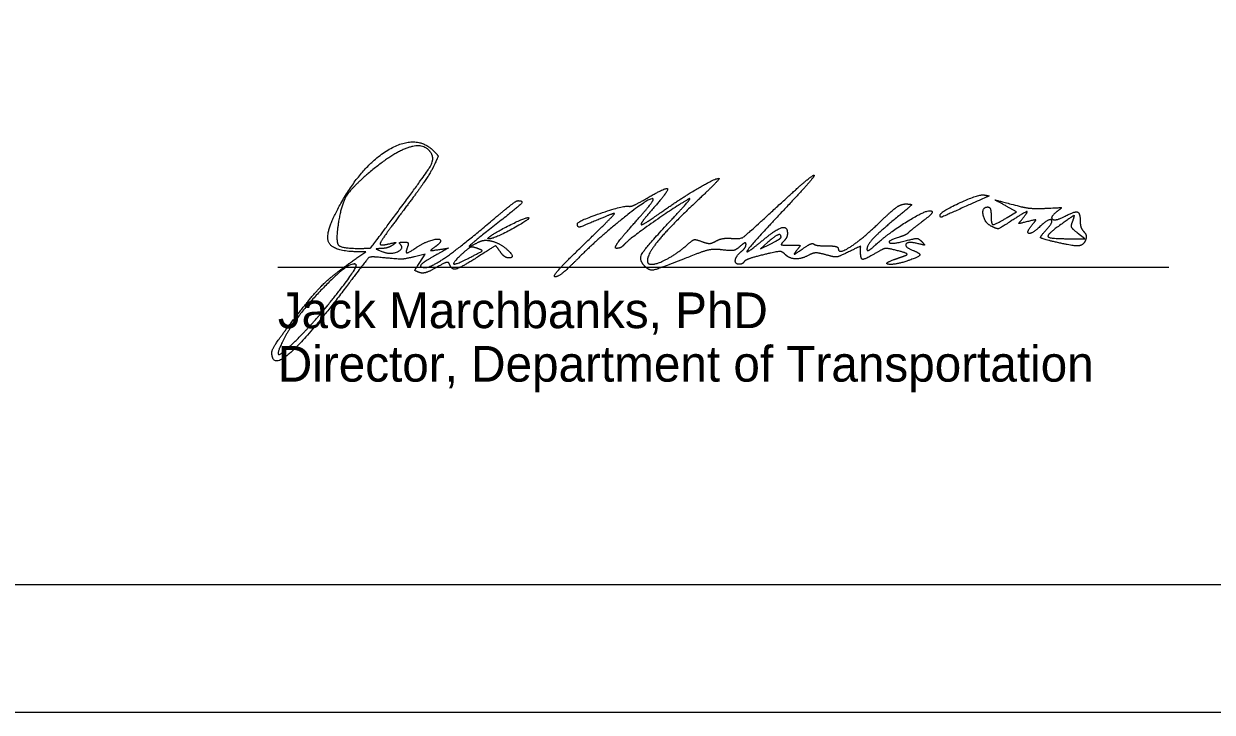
# Model space of a CAD drawing. Extents: x 0 to 34, y 0 to 22.
# Drawn here: x 25.002 to 29.67, y 0 to 2.703 of the extents above; entities that cross this region are included whole.
import ezdxf

# ---------------------------------------------------------------- set-up
doc = ezdxf.new("R2010")
doc.units = 0
for name, color, linetype in [('SH_Border', 7, 'Continuous'), ('SH_Cut_Line', 7, 'Continuous'), ('SH_Data', 7, 'Continuous'), ('SH_Text', 7, 'Continuous')]:
    doc.layers.add(name, color=color, linetype=linetype)

msp = doc.modelspace()

# ---------------------------------------------------------------- linework, layer by layer
at = {"layer": 'SH_Border'}
msp.add_lwpolyline([(1.5, 21.5), (33.5, 21.5), (33.5, 0.5), (1.5, 0.5)], close=True, dxfattribs=at)
at = {"layer": 'SH_Cut_Line'}
msp.add_lwpolyline([(0, 0), (34, 0), (34, 22), (0, 22)], close=True, dxfattribs=at)
at = {"layer": 'SH_Data'}
msp.add_line((26, 1.7478), (29.5, 1.7478), dxfattribs=at)
at = {"layer": 'SH_Text'}
for p, q in [((26.4623, 1.9529), (26.4623, 1.9529)), ((28.6016, 1.952), (28.6016, 1.952)), ((26.7828, 1.8214), (26.7828, 1.8214)), ((26.8276, 1.863), (26.8276, 1.863)), ((27.1995, 1.834), (27.1995, 1.834)), ((27.9766, 1.865), (27.9766, 1.865)), ((29.0541, 1.8458), (29.0541, 1.8458))]:
    msp.add_line(p, q, dxfattribs=at)
for points in [[(28.8654, 1.9425), (28.9018, 1.964), (28.8611, 1.9869)], [(29.1141, 1.8589), (29.1703, 1.859), (29.1416, 1.8811)], [(27.9248, 1.8453), (27.8953, 1.8197), (27.936, 1.8394)], [(26.3146, 1.7859), (26.3453, 1.8071), (26.3075, 1.8078)], [(26.5576, 1.7661), (26.5788, 1.7984), (26.5371, 1.7883)]]:
    msp.add_lwpolyline(points, dxfattribs=at)
for points in [[(26.251, 2.0036), (26.3372, 2.154), (26.5454, 2.27), (26.611, 2.2044)], [(26.6021, 2.1952), (26.5761, 2.2372), (26.45, 2.1961), (26.3547, 2.1144)], [(26.4623, 1.9529), (26.5837, 2.1163), (26.6161, 2.1725), (26.6021, 2.1952)], [(26.611, 2.2044), (26.6298, 2.1856), (26.6298, 2.1806), (26.6115, 2.1421)], [(26.3547, 2.1144), (26.288, 2.0574), (26.2492, 1.9933), (26.2381, 1.922)], [(26.6115, 2.1421), (26.6006, 2.1191), (26.5488, 2.0436), (26.4966, 1.9742)], [(27.959, 1.9825), (28.034, 2.0516), (28.1, 2.1082), (28.1058, 2.1083)], [(28.1058, 2.1083), (28.1115, 2.1084), (28.0595, 2.0482), (27.9901, 1.9746)], [(27.4458, 2.0156), (27.5245, 2.0618), (27.5368, 2.0485), (27.4775, 1.9812)], [(27.5047, 1.9621), (27.5853, 2.0187), (27.7166, 2.096), (27.7323, 2.096)], [(27.7323, 2.096), (27.7372, 2.096), (27.6959, 2.0533), (27.6405, 2.0012)], [(26.8411, 1.9301), (26.8916, 1.973), (26.9371, 2.0082), (26.9422, 2.0083)], [(26.9422, 2.0083), (26.9671, 2.0088), (26.9437, 1.9832), (26.8578, 1.9159)], [(27.4738, 2.0154), (27.4642, 2.025), (27.2545, 1.858), (27.1766, 1.7788)], [(27.6141, 2.0149), (27.565, 1.9871), (27.3767, 1.8549), (27.3635, 1.839)], [(27.3801, 1.9864), (27.3857, 1.9846), (27.4152, 1.9977), (27.4458, 2.0156)], [(27.396, 1.915), (27.4423, 1.9667), (27.4773, 2.0119), (27.4738, 2.0154)], [(27.5489, 1.936), (27.5951, 1.9852), (27.6244, 2.0208), (27.6141, 2.0149)], [(28.6016, 1.952), (28.6016, 1.9644), (28.7544, 2.0347), (28.7733, 2.031)], [(28.7733, 2.031), (28.794, 2.027), (28.7948, 2.0274), (28.6731, 1.9728)], [(28.8611, 1.9869), (28.8182, 2.011), (28.8173, 2.0111), (28.9203, 1.9847)], [(26.3075, 1.8078), (26.2096, 1.8095), (26.1862, 1.8906), (26.251, 2.0036)], [(26.4966, 1.9742), (26.4443, 1.9049), (26.4016, 1.8442), (26.4016, 1.8394)], [(27.1768, 1.9178), (27.177, 1.9284), (27.3644, 1.9915), (27.3801, 1.9864)], [(27.4775, 1.9812), (27.4495, 1.9494), (27.4266, 1.9197), (27.4266, 1.9153)], [(27.4266, 1.9153), (27.4266, 1.9108), (27.4617, 1.9319), (27.5047, 1.9621)], [(27.6405, 2.0012), (27.5409, 1.9075), (27.4516, 1.7994), (27.4516, 1.7724)], [(27.784, 1.8601), (27.8175, 1.8573), (27.8409, 1.8737), (27.959, 1.9825)], [(27.9901, 1.9746), (27.8606, 1.8371), (27.8285, 1.7898), (27.9107, 1.8575)], [(28.3485, 1.8351), (28.4021, 1.8839), (28.549, 1.9739), (28.5659, 1.9683)], [(28.3672, 1.9263), (28.4124, 1.9701), (28.4496, 1.9957), (28.4672, 1.9954)], [(28.4672, 1.9954), (28.4915, 1.9949), (28.4877, 1.9886), (28.4391, 1.9485)], [(28.5659, 1.9683), (28.5743, 1.9655), (28.5591, 1.9467), (28.532, 1.9265)], [(28.6731, 1.9728), (28.6106, 1.9447), (28.6016, 1.9421), (28.6016, 1.952)], [(28.8026, 1.9079), (28.7761, 1.9221), (28.7651, 1.9835), (28.7891, 1.9835)], [(28.7891, 1.9835), (28.796, 1.9835), (28.8016, 1.9694), (28.8016, 1.9522)], [(28.925, 1.9376), (28.9494, 1.9672), (28.9336, 1.9635), (28.8773, 1.9262)], [(28.9203, 1.9847), (28.941, 1.9794), (28.986, 1.9766), (29.0203, 1.9786)], [(29.0203, 1.9786), (29.0752, 1.9816), (29.0801, 1.98), (29.0602, 1.9652)], [(29.0602, 1.9652), (29.0314, 1.9437), (29.0543, 1.9274), (29.088, 1.9454)], [(29.088, 1.9454), (29.1282, 1.9669), (29.1516, 1.9611), (29.1516, 1.9297)], [(26.2381, 1.922), (26.2267, 1.8487), (26.2481, 1.821), (26.3162, 1.821)], [(26.3162, 1.821), (26.3628, 1.821), (26.3674, 1.8251), (26.4623, 1.9529)], [(26.5797, 1.746), (26.6028, 1.746), (26.7289, 1.8348), (26.8411, 1.9301)], [(26.8578, 1.9159), (26.7646, 1.8429), (26.7432, 1.8214), (26.7871, 1.8449)], [(26.8276, 1.863), (26.848, 1.8809), (26.9801, 1.9466), (26.9852, 1.9415)], [(26.9852, 1.9415), (26.9914, 1.9353), (26.8488, 1.8585), (26.8311, 1.8585)], [(27.2578, 1.9335), (27.1952, 1.9066), (27.1765, 1.903), (27.1768, 1.9178)], [(27.1995, 1.834), (27.2705, 1.9024), (27.3258, 1.9585), (27.3224, 1.9585)], [(27.3224, 1.9585), (27.319, 1.9585), (27.2899, 1.9472), (27.2578, 1.9335)], [(27.3302, 1.821), (27.3199, 1.821), (27.3488, 1.8622), (27.396, 1.915)], [(27.4418, 1.7504), (27.4166, 1.7756), (27.4455, 1.8257), (27.5489, 1.936)], [(28.2016, 1.8195), (28.2016, 1.7966), (28.2969, 1.8581), (28.3672, 1.9263)], [(28.4391, 1.9485), (28.3651, 1.8876), (28.3141, 1.8341), (28.3141, 1.8173)], [(28.532, 1.9265), (28.505, 1.9063), (28.48, 1.8864), (28.4766, 1.8821)], [(28.8016, 1.9522), (28.8016, 1.9154), (28.8159, 1.9132), (28.8654, 1.9425)], [(28.8773, 1.9262), (28.8373, 1.8997), (28.824, 1.8965), (28.8026, 1.9079)], [(28.9444, 1.9259), (28.9113, 1.9177), (28.9095, 1.9188), (28.925, 1.9376)], [(28.9645, 1.9152), (28.9791, 1.9328), (28.9768, 1.934), (28.9444, 1.9259)], [(28.9932, 1.9064), (28.9613, 1.8765), (28.9382, 1.8835), (28.9645, 1.9152)], [(29.0184, 1.8938), (29.0489, 1.9275), (29.0272, 1.9384), (28.9932, 1.9064)], [(29.1219, 1.9266), (29.1317, 1.9524), (29.1235, 1.9493), (29.0609, 1.9038)], [(29.1416, 1.8811), (29.1212, 1.8968), (29.1155, 1.91), (29.1219, 1.9266)], [(29.1516, 1.9297), (29.1516, 1.9139), (29.158, 1.8946), (29.1657, 1.8868)], [(27.9107, 1.8575), (27.9591, 1.8974), (28.0016, 1.9078), (28.0016, 1.8797)], [(27.9766, 1.865), (27.9766, 1.8785), (27.9525, 1.8693), (27.9248, 1.8453)], [(28.0016, 1.8797), (28.0016, 1.8708), (27.9948, 1.8567), (27.9866, 1.8485)], [(28.4766, 1.8821), (28.4732, 1.8778), (28.4577, 1.8704), (28.4422, 1.8655)], [(29.0541, 1.8458), (28.9994, 1.8587), (28.9936, 1.8664), (29.0184, 1.8938)], [(29.0609, 1.9038), (29.0182, 1.8727), (29.0347, 1.8588), (29.1141, 1.8589)], [(29.1657, 1.8868), (29.1735, 1.879), (29.1765, 1.8638), (29.1724, 1.853)], [(26.4016, 1.8394), (26.4016, 1.8347), (26.4171, 1.8343), (26.436, 1.8387)], [(26.4516, 1.834), (26.4413, 1.827), (26.4216, 1.8209), (26.4078, 1.8204)], [(26.412, 1.8077), (26.4419, 1.7957), (26.4981, 1.8203), (26.4807, 1.8377)], [(26.436, 1.8387), (26.4615, 1.8447), (26.4655, 1.8434), (26.4516, 1.834)], [(26.4807, 1.8377), (26.4761, 1.8422), (26.4824, 1.846), (26.4946, 1.846)], [(26.4946, 1.846), (26.5092, 1.846), (26.5143, 1.8395), (26.5096, 1.8272)], [(26.5096, 1.8272), (26.5006, 1.8039), (26.5135, 1.8033), (26.5457, 1.8253)], [(26.5457, 1.8253), (26.5746, 1.8451), (26.6391, 1.8626), (26.6391, 1.8507)], [(26.6175, 1.8266), (26.5986, 1.8128), (26.6005, 1.8115), (26.6331, 1.8165)], [(26.6391, 1.8507), (26.6391, 1.8462), (26.6294, 1.8353), (26.6175, 1.8266)], [(26.6331, 1.8165), (26.6699, 1.822), (26.6697, 1.8218), (26.6243, 1.7966)], [(26.7828, 1.8214), (26.7656, 1.8277), (26.7491, 1.8226), (26.7297, 1.8048)], [(26.7547, 1.7851), (26.8011, 1.8087), (26.8047, 1.8133), (26.7828, 1.8214)], [(26.7871, 1.8449), (26.7997, 1.8516), (26.8236, 1.8537), (26.8402, 1.8495)], [(26.8732, 1.8081), (26.8564, 1.8322), (26.8543, 1.8317), (26.7886, 1.7894)], [(26.8311, 1.8585), (26.8263, 1.8585), (26.8248, 1.8605), (26.8276, 1.863)], [(26.8402, 1.8495), (26.8763, 1.8404), (26.9347, 1.7835), (26.908, 1.7835)], [(27.0891, 1.7092), (27.0788, 1.7094), (27.1284, 1.7655), (27.1995, 1.834)], [(27.3635, 1.839), (27.3553, 1.8291), (27.3403, 1.821), (27.3302, 1.821)], [(27.4696, 1.7585), (27.4914, 1.7585), (27.5727, 1.8037), (27.6091, 1.836)], [(27.6091, 1.836), (27.6294, 1.854), (27.6423, 1.8566), (27.666, 1.8476)], [(27.666, 1.8476), (27.6862, 1.8399), (27.705, 1.8406), (27.721, 1.8497)], [(27.721, 1.8497), (27.7344, 1.8572), (27.7627, 1.8619), (27.784, 1.8601)], [(27.8165, 1.8294), (27.8008, 1.8152), (27.7796, 1.8108), (27.747, 1.815)], [(27.8391, 1.8369), (27.8391, 1.844), (27.8289, 1.8406), (27.8165, 1.8294)], [(27.8203, 1.8085), (27.8307, 1.817), (27.8391, 1.8298), (27.8391, 1.8369)], [(27.936, 1.8394), (27.9583, 1.8502), (27.9766, 1.8618), (27.9766, 1.865)], [(27.9866, 1.8485), (27.9749, 1.8368), (27.9808, 1.8335), (28.0131, 1.8335)], [(28.0131, 1.8335), (28.0507, 1.8335), (28.053, 1.8314), (28.0375, 1.8121)], [(28.0592, 1.8179), (28.0807, 1.8329), (28.1014, 1.842), (28.1053, 1.8381)], [(28.1053, 1.8381), (28.1092, 1.8342), (28.1325, 1.831), (28.157, 1.831)], [(28.157, 1.831), (28.1815, 1.831), (28.2016, 1.8258), (28.2016, 1.8195)], [(28.2891, 1.8069), (28.2891, 1.8298), (28.288, 1.8298), (28.2419, 1.807)], [(28.3141, 1.8173), (28.3141, 1.8099), (28.3296, 1.8179), (28.3485, 1.8351)], [(28.4342, 1.8119), (28.3954, 1.8218), (28.3786, 1.8202), (28.351, 1.8039)], [(28.4422, 1.8655), (28.3927, 1.8501), (28.4122, 1.8364), (28.464, 1.8503)], [(28.464, 1.8503), (28.5024, 1.8605), (28.5176, 1.8599), (28.5296, 1.8476)], [(28.511, 1.8402), (28.4742, 1.8492), (28.461, 1.8262), (28.4953, 1.813)], [(28.5296, 1.8476), (28.5423, 1.8347), (28.5388, 1.8333), (28.511, 1.8402)], [(29.1724, 1.853), (29.1643, 1.832), (29.1231, 1.8294), (29.0541, 1.8458)], [(26.0637, 1.5437), (26.1414, 1.6442), (26.2214, 1.7215), (26.3146, 1.7859)], [(26.3959, 1.786), (26.3625, 1.7894), (26.3507, 1.7789), (26.2741, 1.6772)], [(26.4078, 1.8204), (26.3854, 1.8195), (26.3859, 1.8182), (26.412, 1.8077)], [(26.5371, 1.7883), (26.4967, 1.7786), (26.4744, 1.7782), (26.3959, 1.786)], [(26.6243, 1.7966), (26.5732, 1.7684), (26.5535, 1.746), (26.5797, 1.746)], [(26.7886, 1.7894), (26.7197, 1.745), (26.6822, 1.7353), (26.6741, 1.7596)], [(26.7297, 1.8048), (26.6855, 1.7643), (26.6967, 1.7555), (26.7547, 1.7851)], [(26.908, 1.7835), (26.8984, 1.7835), (26.8827, 1.7946), (26.8732, 1.8081)], [(27.1766, 1.7788), (27.1388, 1.7403), (27.0994, 1.709), (27.0891, 1.7092)], [(27.6415, 1.7978), (27.4954, 1.7402), (27.4604, 1.7318), (27.4418, 1.7504)], [(27.747, 1.815), (27.7178, 1.8187), (27.678, 1.8123), (27.6415, 1.7978)], [(27.8134, 1.7585), (27.795, 1.7585), (27.7995, 1.7912), (27.8203, 1.8085)], [(27.9077, 1.7959), (27.8693, 1.7867), (27.835, 1.7745), (27.8315, 1.7688)], [(27.992, 1.798), (27.9809, 1.8092), (27.9608, 1.8087), (27.9077, 1.7959)], [(28.0883, 1.7955), (28.0576, 1.7791), (28.0097, 1.7803), (27.992, 1.798)], [(28.0375, 1.8121), (28.0255, 1.7971), (28.032, 1.7988), (28.0592, 1.8179)], [(28.1528, 1.7956), (28.1259, 1.8033), (28.1028, 1.8033), (28.0883, 1.7955)], [(28.2419, 1.807), (28.2045, 1.7885), (28.1859, 1.7861), (28.1528, 1.7956)], [(28.351, 1.8039), (28.306, 1.7773), (28.2891, 1.7781), (28.2891, 1.8069)], [(28.4702, 1.7709), (28.4236, 1.7555), (28.3763, 1.7613), (28.4203, 1.7769)], [(28.4203, 1.7769), (28.4341, 1.7818), (28.4538, 1.7889), (28.4641, 1.7927)], [(28.4641, 1.7927), (28.4755, 1.7968), (28.4638, 1.8044), (28.4342, 1.8119)], [(28.4953, 1.813), (28.5259, 1.8013), (28.517, 1.7863), (28.4702, 1.7709)], [(26.3075, 1.7567), (26.2866, 1.7776), (26.0681, 1.5519), (26.0218, 1.4616)], [(26.0919, 1.4803), (26.1595, 1.5494), (26.3152, 1.749), (26.3075, 1.7567)], [(26.5564, 1.726), (26.5382, 1.733), (26.5383, 1.7367), (26.5576, 1.7661)], [(26.623, 1.7458), (26.5973, 1.7307), (26.5674, 1.7218), (26.5564, 1.726)], [(26.6741, 1.7596), (26.6713, 1.7682), (26.652, 1.763), (26.623, 1.7458)], [(27.4516, 1.7724), (27.4516, 1.7647), (27.4597, 1.7585), (27.4696, 1.7585)], [(27.8315, 1.7688), (27.828, 1.7631), (27.8198, 1.7585), (27.8134, 1.7585)], [(26.2741, 1.6772), (26.1217, 1.4751), (25.9766, 1.3465), (25.9766, 1.4135)], [(25.9766, 1.4135), (25.9766, 1.4231), (26.0158, 1.4817), (26.0637, 1.5437)], [(26.0218, 1.4616), (25.9905, 1.4006), (26.0222, 1.4091), (26.0919, 1.4803)]]:
    msp.add_open_spline(points, degree=2, dxfattribs=at)

# ---------------------------------------------------------------- texts
for s, p in [('Jack Marchbanks, PhD', (26, 1.5078)), ('Director, Department of Transportation', (26, 1.2978))]:
    msp.add_text(s, height=0.14, dxfattribs=at).set_placement(p)

doc.saveas('drawing.dxf')
